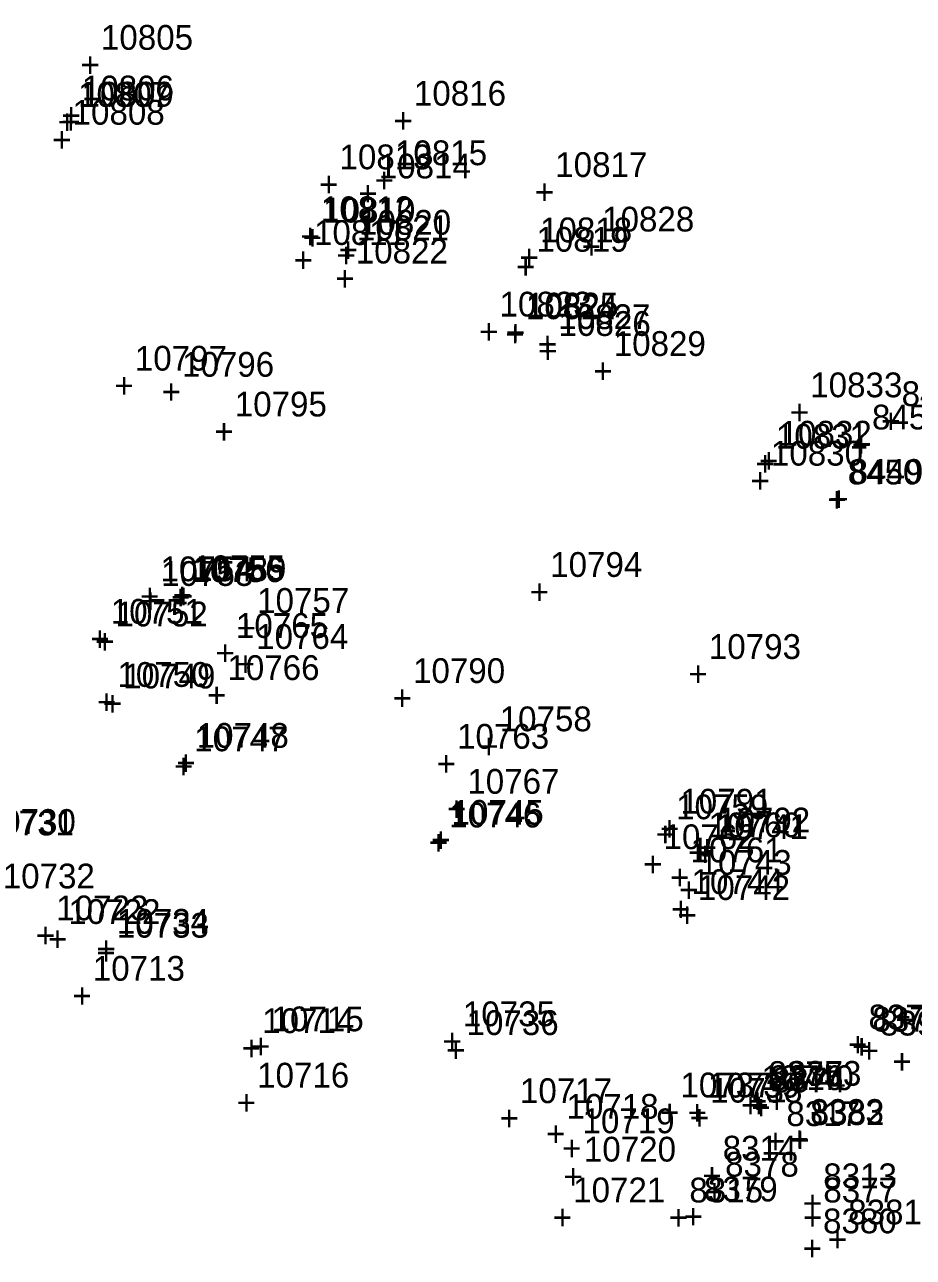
# Model space of a CAD drawing. Extents: x 1136220 to 1137808, y 528804 to 531215.
# Drawn here: x 1137087 to 1137176.7, y 530409.7 to 530534.2 of the extents above; entities that cross this region are included whole.
import ezdxf

# ---------------------------------------------------------------- set-up
doc = ezdxf.new("R2010")
doc.units = 0
for name, color, linetype in [('S_Curb_Type_1', 7, 'Continuous'), ('S_Curb_Type_3', 7, 'Continuous'), ('S_Drainage_CB', 7, 'Continuous'), ('S_Ground_Elevation', 7, 'Continuous'), ('S_Ground_LevelString', 7, 'Continuous'), ('S_Ground_SpotElevation', 7, 'Continuous'), ('S_Property_Garden', 7, 'Continuous'), ('S_Property_Light', 7, 'Continuous'), ('S_Roadway_Centerline', 7, 'Continuous'), ('S_Roadway_Drive_Paved', 7, 'Continuous'), ('S_Roadway_Edge_Pavement', 7, 'Continuous'), ('S_Roadway_Sidewalks', 7, 'Continuous'), ('S_Traffic_Sign_SinglePost', 7, 'Continuous'), ('S_Trees_Decid_NonPay', 7, 'Continuous'), ('S_Utilities_GuyWire3', 7, 'Continuous'), ('S_Utilities_Pole_Power', 7, 'Continuous'), ('S_Utilities_UG_Sanitary_MH', 7, 'Continuous'), ('S_Utilities_UG_Water_Gate', 7, 'Continuous')]:
    doc.layers.add(name, color=color, linetype=linetype)

msp = doc.modelspace()

# ---------------------------------------------------------------- texts
at = {"layer": 'S_Curb_Type_1'}
for s, p in [('10806', (1137092.82, 530526.51)), ('+', (1137090.76, 530523.76)), ('10812', (1137116.94, 530514.32)), ('10820', (1137120.78, 530512.95)), ('+', (1137114.88, 530511.57)), ('+', (1137118.72, 530510.2)), ('10825', (1137137.65, 530504.6)), ('10826', (1137140.92, 530502.74)), ('+', (1137135.59, 530501.85)), ('+', (1137138.86, 530499.99)), ('10832', (1137163.22, 530491.67)), ('+', (1137161.15, 530488.92)), ('8449', (1137170.28, 530487.81)), ('+', (1137168.22, 530485.06)), ('10757', (1137110.5, 530474.79)), ('+', (1137108.44, 530472.04)), ('10765', (1137108.36, 530472.26)), ('10764', (1137110.4, 530471.15)), ('+', (1137106.3, 530469.51)), ('+', (1137108.34, 530468.4)), ('10758', (1137134.97, 530462.84)), ('10763', (1137130.67, 530461.08)), ('+', (1137132.91, 530460.09)), ('+', (1137128.61, 530458.33)), ('10759', (1137152.77, 530453.96)), ('10760', (1137156.05, 530452.14)), ('+', (1137150.71, 530451.21)), ('10762', (1137151.51, 530450.94)), ('+', (1137153.99, 530449.39)), ('10761', (1137154.23, 530449.61)), ('+', (1137149.45, 530448.19)), ('+', (1137152.17, 530446.86)), ('8372', (1137172.58, 530432.53)), ('+', (1137174.9, 530432.51)), ('+', (1137170.52, 530429.78))]:
    msp.add_text(s, height=2.5, dxfattribs=at).set_placement(p)
at = {"layer": 'S_Curb_Type_3'}
for s, p in [('10753', (1137100.82, 530477.51)), ('10756', (1137103.87, 530477.89)), ('+', (1137098.75, 530474.76)), ('+', (1137101.81, 530475.14)), ('10752', (1137096.22, 530473.42)), ('+', (1137094.16, 530470.67)), ('10749', (1137096.99, 530467.16)), ('+', (1137094.93, 530464.41)), ('10748', (1137104.4, 530461.17)), ('+', (1137102.34, 530458.42)), ('10745', (1137130.12, 530453.4)), ('10731', (1137082.73, 530452.33)), ('+', (1137128.06, 530450.65)), ('10743', (1137155.14, 530448.35)), ('10744', (1137154.33, 530446.41)), ('+', (1137153.08, 530445.6)), ('+', (1137152.27, 530443.66)), ('10733', (1137096.34, 530442.01)), ('+', (1137094.28, 530439.26)), ('10736', (1137131.63, 530432.18)), ('+', (1137129.57, 530429.43)), ('8373', (1137164.03, 530427.06)), ('10737', (1137153.21, 530425.89)), ('10738', (1137156.22, 530425.36)), ('8374', (1137162.43, 530426.39)), ('+', (1137151.15, 530423.14)), ('+', (1137160.37, 530423.64)), ('+', (1137161.97, 530424.31)), ('+', (1137154.16, 530422.61))]:
    msp.add_text(s, height=2.5, dxfattribs=at).set_placement(p)
at = {"layer": 'S_Drainage_CB'}
for s, p in [('10823', (1137134.96, 530504.7)), ('+', (1137132.9, 530501.95))]:
    msp.add_text(s, height=2.5, dxfattribs=at).set_placement(p)
at = {"layer": 'S_Ground_Elevation'}
for s, p in [('8452', (1137175.53, 530495.66)), ('+', (1137173.47, 530492.91)), ('8390', (1137173.34, 530432.13)), ('+', (1137171.28, 530429.38)), ('8383', (1137166.3, 530423.21)), ('8382', (1137166.36, 530423.1)), ('+', (1137164.24, 530420.46)), ('+', (1137164.3, 530420.35))]:
    msp.add_text(s, height=2.5, dxfattribs=at).set_placement(p)
at = {"layer": 'S_Ground_LevelString'}
for s, p in [('10809', (1137092.79, 530525.89)), ('+', (1137090.73, 530523.14)), ('10810', (1137117.16, 530514.18)), ('10821', (1137120.57, 530512.4)), ('+', (1137115.1, 530511.43)), ('+', (1137118.51, 530509.65)), ('10824', (1137137.61, 530504.43)), ('+', (1137135.55, 530501.68)), ('10831', (1137162.84, 530491.36)), ('+', (1137160.78, 530488.61))]:
    msp.add_text(s, height=2.5, dxfattribs=at).set_placement(p)
at = {"layer": 'S_Ground_SpotElevation'}
for s, p in [('8381', (1137170.14, 530413.07)), ('+', (1137168.08, 530410.32))]:
    msp.add_text(s, height=2.5, dxfattribs=at).set_placement(p)
at = {"layer": 'S_Property_Garden'}
for s, p in [('8378', (1137157.72, 530417.89)), ('8379', (1137155.59, 530415.39)), ('8377', (1137167.63, 530415.28)), ('+', (1137155.66, 530415.14)), ('+', (1137153.53, 530412.64)), ('+', (1137165.57, 530412.53)), ('8380', (1137167.6, 530412.17)), ('+', (1137165.54, 530409.42))]:
    msp.add_text(s, height=2.5, dxfattribs=at).set_placement(p)
at = {"layer": 'S_Property_Light'}
for s, p in [('10732', (1137084.83, 530446.98)), ('+', (1137174.59, 530428.28))]:
    msp.add_text(s, height=2.5, dxfattribs=at).set_placement(p)
at = {"layer": 'S_Roadway_Centerline'}
for s, p in [('10795', (1137108.24, 530494.61)), ('+', (1137106.18, 530491.86)), ('10794', (1137140.07, 530478.42)), ('+', (1137138.01, 530475.67)), ('10793', (1137156.08, 530470.14)), ('+', (1137154.02, 530467.39))]:
    msp.add_text(s, height=2.5, dxfattribs=at).set_placement(p)
at = {"layer": 'S_Roadway_Drive_Paved'}
for s, p in [('10816', (1137126.32, 530525.98)), ('+', (1137124.26, 530523.23)), ('10815', (1137124.41, 530519.97)), ('10817', (1137140.58, 530518.78)), ('+', (1137122.35, 530517.22)), ('+', (1137138.52, 530516.03)), ('10818', (1137139.04, 530512.19)), ('+', (1137136.97, 530509.44)), ('10754', (1137100.75, 530477.98)), ('10755', (1137104.03, 530478.09)), ('+', (1137098.69, 530475.23)), ('+', (1137101.97, 530475.34)), ('10751', (1137095.73, 530473.69)), ('+', (1137093.66, 530470.94)), ('10750', (1137096.4, 530467.32)), ('+', (1137094.34, 530464.57)), ('10747', (1137104.16, 530460.82)), ('+', (1137102.1, 530458.07)), ('10746', (1137129.88, 530453.13)), ('10730', (1137082.91, 530452.48)), ('10741', (1137156.79, 530451.96)), ('+', (1137127.82, 530450.38)), ('+', (1137154.73, 530449.21)), ('10742', (1137154.98, 530445.81)), ('+', (1137152.92, 530443.06)), ('10734', (1137096.35, 530442.4)), ('+', (1137094.29, 530439.65)), ('10735', (1137131.26, 530433.07)), ('8371', (1137172.19, 530432.75)), ('+', (1137174.53, 530432.78)), ('+', (1137129.2, 530430.32)), ('+', (1137170.13, 530430)), ('10740', (1137161.39, 530426.62)), ('8375', (1137162.08, 530427.04)), ('10739', (1137155.99, 530425.87)), ('+', (1137159.32, 530423.87)), ('+', (1137160.02, 530424.29)), ('+', (1137153.93, 530423.12))]:
    msp.add_text(s, height=2.5, dxfattribs=at).set_placement(p)
at = {"layer": 'S_Roadway_Edge_Pavement'}
for s, p in [('10807', (1137092.43, 530525.86)), ('10808', (1137091.88, 530524.06)), ('+', (1137090.37, 530523.11)), ('+', (1137089.82, 530521.31)), ('10811', (1137116.24, 530511.92)), ('10822', (1137120.45, 530510.05)), ('+', (1137114.18, 530509.17)), ('+', (1137118.38, 530507.3)), ('10830', (1137162.34, 530489.65)), ('8450', (1137170.09, 530487.75)), ('+', (1137160.28, 530486.9)), ('+', (1137168.03, 530485)), ('10789', (1137104.16, 530477.99)), ('+', (1137102.1, 530475.24)), ('10790', (1137126.23, 530467.71)), ('+', (1137124.17, 530464.96)), ('10791', (1137153.2, 530454.53)), ('10792', (1137157.01, 530452.63)), ('+', (1137151.14, 530451.78)), ('+', (1137154.95, 530449.88))]:
    msp.add_text(s, height=2.5, dxfattribs=at).set_placement(p)
at = {"layer": 'S_Roadway_Sidewalks'}
for s, p in [('10805', (1137094.74, 530531.62)), ('+', (1137092.68, 530528.87)), ('10813', (1137118.81, 530519.56)), ('10814', (1137122.77, 530518.64)), ('+', (1137116.75, 530516.81)), ('+', (1137120.7, 530515.89)), ('10819', (1137138.68, 530511.24)), ('+', (1137136.62, 530508.49)), ('10833', (1137166.31, 530496.55)), ('+', (1137164.25, 530493.8)), ('8451', (1137172.54, 530493.3)), ('+', (1137170.48, 530490.55)), ('10723', (1137090.23, 530443.76)), ('10722', (1137091.45, 530443.39)), ('+', (1137088.17, 530441.01)), ('+', (1137089.39, 530440.64)), ('10713', (1137093.92, 530437.66)), ('+', (1137091.86, 530434.91)), ('10714', (1137111.01, 530432.37)), ('+', (1137108.95, 530429.62)), ('8316', (1137162.22, 530426.62)), ('10717', (1137137.02, 530425.31)), ('10718', (1137141.71, 530423.73)), ('+', (1137160.16, 530423.87)), ('8317', (1137163.9, 530422.99)), ('+', (1137134.96, 530422.56)), ('10719', (1137143.33, 530422.27)), ('+', (1137139.65, 530420.98)), ('+', (1137141.27, 530419.52)), ('10720', (1137143.47, 530419.41)), ('8314', (1137157.48, 530419.51)), ('+', (1137161.84, 530420.24)), ('8313', (1137167.62, 530416.72)), ('+', (1137141.41, 530416.66)), ('10721', (1137142.39, 530415.3)), ('8315', (1137154.11, 530415.28)), ('+', (1137155.42, 530416.76)), ('+', (1137165.56, 530413.97)), ('+', (1137140.33, 530412.55)), ('+', (1137152.04, 530412.53))]:
    msp.add_text(s, height=2.5, dxfattribs=at).set_placement(p)
at = {"layer": 'S_Traffic_Sign_SinglePost'}
for s, p in [('10829', (1137146.48, 530500.72)), ('+', (1137144.42, 530497.97))]:
    msp.add_text(s, height=2.5, dxfattribs=at).set_placement(p)
at = {"layer": 'S_Trees_Decid_NonPay'}
for s, p in [('10766', (1137107.5, 530468.01)), ('+', (1137105.44, 530465.26)), ('10767', (1137131.71, 530456.53)), ('+', (1137129.65, 530453.78))]:
    msp.add_text(s, height=2.5, dxfattribs=at).set_placement(p)
at = {"layer": 'S_Utilities_GuyWire3'}
for s, p in [('10828', (1137145.31, 530513.28)), ('+', (1137143.25, 530510.53)), ('10716', (1137110.5, 530426.88)), ('+', (1137108.44, 530424.13))]:
    msp.add_text(s, height=2.5, dxfattribs=at).set_placement(p)
at = {"layer": 'S_Utilities_Pole_Power'}
for s, p in [('10827', (1137140.88, 530503.43)), ('+', (1137138.82, 530500.68)), ('10715', (1137111.96, 530432.56)), ('+', (1137109.89, 530429.81))]:
    msp.add_text(s, height=2.5, dxfattribs=at).set_placement(p)
at = {"layer": 'S_Utilities_UG_Sanitary_MH'}
for s, p in [('10796', (1137102.92, 530498.62)), ('+', (1137100.86, 530495.87))]:
    msp.add_text(s, height=2.5, dxfattribs=at).set_placement(p)
at = {"layer": 'S_Utilities_UG_Water_Gate'}
for s, p in [('10797', (1137098.16, 530499.24)), ('+', (1137096.1, 530496.49))]:
    msp.add_text(s, height=2.5, dxfattribs=at).set_placement(p)

doc.saveas('drawing.dxf')
